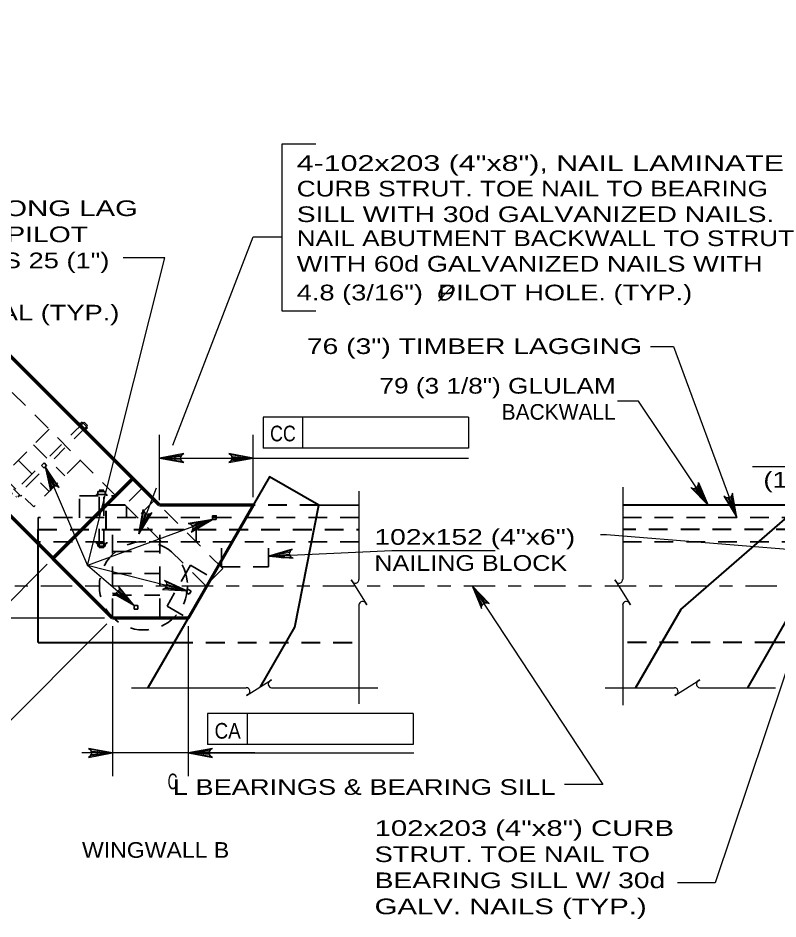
# Model space of a CAD drawing. Extents: x -6.4 to 73.1, y -66 to 0.
# Drawn here: x 21.96 to 27.78, y -57.6 to -50.7 of the extents above; entities that cross this region are included whole.
import ezdxf
from ezdxf.enums import TextEntityAlignment as Align

# ---------------------------------------------------------------- set-up
doc = ezdxf.new("R2010")
doc.units = 0
doc.header["$LTSCALE"] = 0.048
doc.linetypes.add('DOT_DASHED', pattern=[7.7, 5, -1.2, 0.3, -1.2])
doc.linetypes.add('MEDIUM_DASHED', pattern=[4.5, 3, -1.5])
for name, color, linetype, lineweight in [('4', 7, 'Continuous', 25), ('5', 7, 'Continuous', 25), ('52', 7, 'Continuous', 25), ('8', 7, 'Continuous', 25)]:
    doc.layers.add(name, color=color, linetype=linetype, lineweight=lineweight)

msp = doc.modelspace()

# ---------------------------------------------------------------- hatches: boundary and pattern name
at = {"layer": '5'}
for points in [[(23.16208, -54.05267), (23.16208, -54.092), (23.044, -54.07233)], [(23.64475, -54.05267), (23.64475, -54.092), (23.76283, -54.07233)], [(22.169, -54.13942), (22.22433, -54.24425), (22.20617, -54.252)], [(27.46675, -54.52792), (27.41658, -54.42058), (27.43508, -54.41375)], [(23.45042, -54.54325), (23.343, -54.59333), (23.33625, -54.57492)], [(23.87967, -54.82492), (23.99817, -54.82042), (23.99725, -54.84008)], [(23.25542, -55.09025), (23.13842, -55.07083), (23.14325, -55.05175)], [(25.43875, -55.05158), (25.51192, -55.14475), (25.4955, -55.15558)], [(22.84892, -55.20325), (22.75283, -55.13392), (22.76558, -55.119)], [(22.56708, -56.31183), (22.56708, -56.35117), (22.68517, -56.3315)], [(23.38083, -56.31183), (23.38083, -56.35117), (23.26275, -56.3315)]]:
    msp.add_hatch(color=256, dxfattribs=at).paths.add_polyline_path(points)

# ---------------------------------------------------------------- linework, layer by layer
at = {"layer": '4', "lineweight": 70}
for p, q in [((23.044, -54.43392), (21.86292, -53.25283)), ((22.68517, -55.30008), (21.25042, -53.86525)), ((22.83983, -54.22975), (22.22733, -54.84225)), ((23.76283, -54.43392), (23.044, -54.43392)), ((23.76283, -54.43392), (23.26275, -55.30008)), ((23.26275, -55.30008), (22.68517, -55.30008))]:
    msp.add_line(p, q, dxfattribs=at)
at = {"layer": '4', "linetype": 'MEDIUM_DASHED', "lineweight": 35}
for p, q in [((22.70825, -54.36133), (21.73133, -53.38433)), ((22.46633, -53.79667), (22.20417, -54.05883)), ((22.49242, -53.82275), (22.2365, -54.07867)), ((22.19875, -53.85175), (21.84175, -54.20875)), ((22.0795, -53.971), (22.318, -54.20958)), ((21.96058, -54.08992), (22.19917, -54.32842)), ((22.43725, -54.09033), (22.08025, -54.44733)), ((22.092, -54.17092), (21.91817, -54.34483)), ((21.84175, -54.20875), (22.08025, -54.44733)), ((22.12125, -54.19392), (21.94425, -54.37092)), ((22.58133, -54.31917), (22.61825, -54.31917)), ((22.58133, -54.75817), (22.58133, -54.31917)), ((22.61825, -54.75817), (22.61825, -54.31917)), ((22.91242, -54.30242), (22.78092, -54.43392)), ((21.95917, -54.37092), (21.97408, -54.356)), ((22.43117, -54.53), (22.43117, -54.36133)), ((22.43117, -54.36133), (22.70825, -54.36133)), ((22.56025, -54.35075), (22.56025, -54.36133)), ((22.56025, -54.35075), (22.63933, -54.35075)), ((22.57083, -54.32967), (22.57083, -54.35075)), ((22.57083, -54.32967), (22.62883, -54.32967)), ((22.62883, -54.32967), (22.62883, -54.35075)), ((22.63933, -54.35075), (22.63933, -54.36133)), ((23.3985, -55.05158), (22.70825, -54.36133)), ((22.79208, -54.53), (22.79208, -54.44508)), ((23.00642, -54.39642), (22.87492, -54.52792)), ((23.53008, -54.92), (23.044, -54.43392)), ((24.57267, -54.52792), (22.11433, -54.52792)), ((23.324, -54.714), (23.324, -54.52792)), ((26.59325, -54.52792), (29.86575, -54.52792)), ((22.68517, -55.29242), (22.68517, -54.61992)), ((23.04608, -55.29242), (23.04608, -54.61992)), ((24.57267, -54.714), (22.11433, -54.714)), ((23.51875, -54.90642), (23.51875, -54.714)), ((23.87967, -54.90642), (23.87967, -54.714)), ((26.59325, -54.714), (29.86575, -54.714)), ((22.68517, -54.78808), (23.04608, -54.78808)), ((23.28208, -54.8945), (23.44325, -54.9875)), ((23.53008, -54.92), (23.3985, -55.05158)), ((23.51875, -54.90642), (23.87967, -54.90642)), ((22.68517, -54.95617), (23.04608, -54.95617)), ((22.68517, -55.12425), (23.04608, -55.12425)), ((22.68517, -55.29242), (23.04608, -55.29242))]:
    msp.add_line(p, q, dxfattribs=at)
at = {"layer": '4', "lineweight": 35}
for p, q in [((22.42908, -53.80408), (22.42158, -53.81158)), ((22.42908, -53.80408), (22.48492, -53.86)), ((22.45142, -53.79667), (22.4365, -53.81158)), ((22.45142, -53.79667), (22.49242, -53.83767)), ((22.46633, -53.79667), (22.49242, -53.82275)), ((22.49242, -53.83767), (22.4775, -53.85258)), ((22.48492, -53.86), (22.4775, -53.86742)), ((24.264, -54.43392), (24.57267, -54.43392)), ((22.11433, -54.714), (22.11433, -54.52792)), ((22.56025, -54.7265), (22.56025, -54.716)), ((22.56025, -54.7265), (22.63933, -54.7265)), ((22.57083, -54.74758), (22.57083, -54.7265)), ((22.62883, -54.74758), (22.62883, -54.7265)), ((22.63933, -54.7265), (22.63933, -54.716)), ((22.57083, -54.74758), (22.62883, -54.74758)), ((22.58133, -54.75817), (22.61825, -54.75817))]:
    msp.add_line(p, q, dxfattribs=at)
at = {"layer": '4', "linetype": 'MEDIUM_DASHED', "lineweight": 40}
for p, q in [((22.78092, -54.43392), (22.63567, -54.43392)), ((22.63567, -54.61992), (22.63567, -54.43392)), ((24.264, -54.43392), (23.76283, -54.43392)), ((22.11433, -54.61992), (24.57267, -54.61992)), ((29.86575, -54.61992), (26.59325, -54.61992)), ((23.15542, -55.48608), (24.57267, -55.48608)), ((27.75108, -55.48608), (26.59325, -55.48608))]:
    msp.add_line(p, q, dxfattribs=at)
at = {"layer": '4', "lineweight": 40}
for p, q in [((24.08183, -55.3695), (24.264, -54.43392)), ((28.35858, -54.43392), (26.59325, -54.43392)), ((27.03808, -55.23275), (27.957, -54.43392)), ((22.11433, -55.48658), (22.11433, -54.61992)), ((27.03808, -55.23275), (26.69225, -55.83192)), ((23.26275, -55.30008), (22.95575, -55.83192)), ((27.55142, -55.83192), (27.8585, -55.30008)), ((23.81925, -55.82433), (24.08183, -55.3695)), ((22.11433, -55.48608), (23.15542, -55.48608)), ((29.86575, -55.48608), (27.75108, -55.48608))]:
    msp.add_line(p, q, dxfattribs=at)
at = {"layer": '4', "linetype": 'DOT_DASHED'}
msp.add_line((21.5955, -55.05158), (30.39275, -55.05158), dxfattribs=at)
at = {"layer": '4'}
for points in [[(27.24908, -54.43392), (26.71425, -53.63683), (26.55433, -53.63683)], [(28.1095, -54.793), (26.4685, -54.6605), (26.42267, -54.6605)]]:
    msp.add_lwpolyline(points, dxfattribs=at)
at = {"layer": '4', "linetype": 'MEDIUM_DASHED', "lineweight": 35}
for points in [[(22.15917, -54.14933), (22.13942, -54.12958), (22.15917, -54.10983), (22.17892, -54.12958)], [(23.26233, -55.07817), (23.24842, -55.10233), (23.27258, -55.11633), (23.2865, -55.09217)], [(22.84892, -55.23117), (22.87683, -55.23117), (22.87683, -55.20325), (22.84892, -55.20325)]]:
    msp.add_lwpolyline(points, close=True, dxfattribs=at)
at = {"layer": '4', "lineweight": 40}
msp.add_lwpolyline([(24.264, -54.43392), (23.88817, -54.21692), (23.76283, -54.43392)], dxfattribs=at)
at = {"layer": '4', "linetype": 'MEDIUM_DASHED', "lineweight": 35}
for points in [[(21.92558, -54.30758), (21.9815, -54.36342), (21.989, -54.356)], [(23.28208, -54.8945), (23.10167, -55.20708), (23.26275, -55.30008)]]:
    msp.add_lwpolyline(points, dxfattribs=at)
at = {"layer": '4', "lineweight": 35}
msp.add_lwpolyline([(23.47833, -54.54325), (23.45042, -54.54325), (23.45042, -54.51533), (23.47833, -54.51533)], close=True, dxfattribs=at)
at = {"layer": '4', "linetype": 'MEDIUM_DASHED', "lineweight": 35}
msp.add_circle((22.92103, -55.05157), 0.3376, dxfattribs=at)
at = {"layer": '5'}
for p, q in [((23.98267, -51.66758), (23.98267, -52.94567)), ((24.24158, -51.66758), (23.98267, -51.66758)), ((23.98267, -52.94567), (24.24158, -52.94567)), ((26.98392, -53.22058), (26.8075, -53.22058)), ((27.46675, -54.52792), (26.984, -53.22058)), ((25.41225, -53.75975), (23.83742, -53.75975)), ((23.83742, -53.75975), (23.83742, -53.996)), ((24.13992, -53.75975), (24.13992, -53.996)), ((25.41225, -53.75975), (25.41225, -53.996)), ((23.04392, -54.395), (23.04392, -53.89517)), ((23.76283, -54.37242), (23.76283, -53.89517)), ((25.41225, -53.996), (23.83742, -53.996)), ((23.044, -54.07233), (25.41208, -54.07233)), ((27.58925, -54.13692), (28.93608, -54.13692)), ((22.88542, -54.65225), (23.02133, -54.29967)), ((23.45042, -54.54325), (22.49117, -54.89692)), ((22.18392, -54.88575), (21.17033, -55.89925)), ((23.25542, -55.09025), (22.49117, -54.89692)), ((22.84892, -55.20325), (22.49117, -54.89692)), ((27.99592, -55.25533), (27.303, -57.32725)), ((22.64167, -55.34358), (21.62817, -56.35708)), ((22.62358, -55.30008), (21.86433, -55.30008)), ((22.68517, -55.36158), (22.68517, -56.50867)), ((23.26275, -55.36158), (23.26275, -56.50867)), ((24.98708, -56.03067), (23.41225, -56.03067)), ((23.41225, -56.03067), (23.41225, -56.26683)), ((23.71467, -56.03067), (23.71467, -56.26683)), ((24.98708, -56.03067), (24.98708, -56.26683)), ((24.98708, -56.26683), (23.41225, -56.26683)), ((22.68517, -56.3315), (22.449, -56.3315)), ((23.77408, -56.3315), (22.68517, -56.3315)), ((23.26275, -56.3315), (24.99225, -56.3315)), ((27.30292, -57.32725), (27.01375, -57.32725))]:
    msp.add_line(p, q, dxfattribs=at)
at = {"layer": '5', "lineweight": 35}
msp.add_line((25.18292, -52.87183), (25.29492, -52.74925), dxfattribs=at)
at = {"layer": '5'}
for points in [[(23.14667, -53.9745), (23.76233, -52.37725), (23.98258, -52.37725)], [(22.169, -54.13942), (22.49117, -54.89692), (23.08542, -52.53858), (22.76583, -52.53858)], [(23.044, -54.07233), (23.23042, -54.10725), (23.21608, -54.09733), (23.20867, -54.08483), (23.2065, -54.07233), (23.20867, -54.05983), (23.21608, -54.04733), (23.23042, -54.03742), (23.044, -54.07233), (23.21608, -54.04733), (23.20867, -54.05983), (23.044, -54.07233), (23.2065, -54.07233), (23.20867, -54.08483), (23.044, -54.07233), (23.21608, -54.09733)], [(23.76283, -54.07233), (23.57642, -54.03742), (23.59075, -54.04733), (23.59817, -54.05983), (23.60033, -54.07233), (23.59817, -54.08483), (23.59075, -54.09733), (23.57642, -54.10725), (23.76283, -54.07233), (23.59075, -54.09733), (23.59817, -54.08483), (23.76283, -54.07233), (23.60033, -54.07233), (23.59817, -54.05983), (23.76283, -54.07233), (23.59075, -54.04733)], [(22.169, -54.13942), (22.20983, -54.32467), (22.21333, -54.3075), (22.22192, -54.29583), (22.23258, -54.28892), (22.24492, -54.286), (22.25933, -54.28792), (22.27408, -54.29725), (22.169, -54.13942), (22.25933, -54.28792), (22.24492, -54.286), (22.169, -54.13942), (22.23258, -54.28892), (22.22192, -54.29583), (22.169, -54.13942), (22.21333, -54.3075)], [(27.46675, -54.52792), (27.435, -54.34092), (27.43058, -54.35783), (27.42142, -54.36917), (27.4105, -54.3755), (27.398, -54.37783), (27.38367, -54.37517), (27.36942, -54.36517), (27.46675, -54.52792), (27.38367, -54.37517), (27.398, -54.37783), (27.46675, -54.52792), (27.4105, -54.3755), (27.42142, -54.36917), (27.46675, -54.52792), (27.43058, -54.35783)], [(23.45042, -54.54325), (23.26342, -54.57492), (23.28033, -54.57933), (23.29158, -54.5885), (23.29792, -54.5995), (23.30025, -54.61192), (23.29767, -54.62625), (23.28758, -54.6405), (23.45042, -54.54325), (23.29767, -54.62625), (23.30025, -54.61192), (23.45042, -54.54325), (23.29792, -54.5995), (23.29158, -54.5885), (23.45042, -54.54325), (23.28033, -54.57933)], [(23.87967, -54.82492), (24.06875, -54.84008), (24.05342, -54.83167), (24.04475, -54.82), (24.04125, -54.80783), (24.04208, -54.79525), (24.04817, -54.782), (24.06142, -54.7705), (23.87967, -54.82492), (24.04817, -54.782), (24.04208, -54.79525), (23.87967, -54.82492), (24.04125, -54.80783), (24.04475, -54.82), (23.87967, -54.82492), (24.05342, -54.83167)], [(23.87967, -54.82492), (24.82492, -54.78008), (25.61717, -54.78008)], [(22.84892, -55.20325), (22.73008, -55.05542), (22.7345, -55.07233), (22.732, -55.08667), (22.7255, -55.09758), (22.71575, -55.10567), (22.702, -55.11033), (22.68458, -55.10858), (22.84892, -55.20325), (22.702, -55.11033), (22.71575, -55.10567), (22.84892, -55.20325), (22.7255, -55.09758), (22.732, -55.08667), (22.84892, -55.20325), (22.7345, -55.07233)], [(23.25542, -55.09025), (23.08325, -55.01067), (23.09475, -55.02383), (23.09883, -55.03775), (23.09792, -55.05042), (23.09275, -55.062), (23.0825, -55.07233), (23.06608, -55.07842), (23.25542, -55.09025), (23.0825, -55.07233), (23.09275, -55.062), (23.25542, -55.09025), (23.09792, -55.05042), (23.09883, -55.03775), (23.25542, -55.09025), (23.09475, -55.02383)], [(25.43875, -55.05158), (26.44075, -56.57292), (26.14758, -56.57292)], [(25.43875, -55.05158), (25.51208, -55.2265), (25.5125, -55.209), (25.51883, -55.196), (25.52817, -55.18733), (25.53975, -55.18217), (25.55425, -55.1815), (25.5705, -55.188), (25.43875, -55.05158), (25.55425, -55.1815), (25.53975, -55.18217), (25.43875, -55.05158), (25.52817, -55.18733), (25.51883, -55.196), (25.43875, -55.05158), (25.5125, -55.209)], [(22.68517, -56.3315), (22.49875, -56.29658), (22.51308, -56.3065), (22.5205, -56.319), (22.52267, -56.3315), (22.5205, -56.344), (22.51308, -56.3565), (22.49875, -56.36642), (22.68517, -56.3315), (22.51308, -56.3565), (22.5205, -56.344), (22.68517, -56.3315), (22.52267, -56.3315), (22.5205, -56.319), (22.68517, -56.3315), (22.51308, -56.3065)], [(23.26275, -56.3315), (23.44917, -56.36642), (23.43483, -56.3565), (23.42742, -56.344), (23.42525, -56.3315), (23.42742, -56.319), (23.43483, -56.3065), (23.44917, -56.29658), (23.26275, -56.3315), (23.43483, -56.3065), (23.42742, -56.319), (23.26275, -56.3315), (23.42525, -56.3315), (23.42742, -56.344), (23.26275, -56.3315), (23.43483, -56.3565)]]:
    msp.add_lwpolyline(points, dxfattribs=at)
for points in [[(23.16208, -54.05267), (23.16208, -54.092), (23.044, -54.07233)], [(23.64475, -54.05267), (23.64475, -54.092), (23.76283, -54.07233)], [(22.169, -54.13942), (22.22433, -54.24425), (22.20617, -54.252)], [(27.46675, -54.52792), (27.41658, -54.42058), (27.43508, -54.41375)], [(23.45042, -54.54325), (23.343, -54.59333), (23.33625, -54.57492)], [(23.87967, -54.82492), (23.99817, -54.82042), (23.99725, -54.84008)], [(23.25542, -55.09025), (23.13842, -55.07083), (23.14325, -55.05175)], [(25.43875, -55.05158), (25.51192, -55.14475), (25.4955, -55.15558)], [(22.84892, -55.20325), (22.75283, -55.13392), (22.76558, -55.119)], [(22.56708, -56.31183), (22.56708, -56.35117), (22.68517, -56.3315)], [(23.38083, -56.31183), (23.38083, -56.35117), (23.26275, -56.3315)]]:
    msp.add_lwpolyline(points, close=True, dxfattribs=at)
at = {"layer": '5', "lineweight": 35}
msp.add_spline([(25.28325, -52.76133), (25.2745, -52.7545), (25.26575, -52.75208), (25.25475, -52.75108), (25.2485, -52.75108), (25.23775, -52.75358), (25.22792, -52.75808), (25.221, -52.762), (25.20775, -52.77258), (25.19742, -52.78608), (25.19117, -52.79875), (25.1875, -52.81033), (25.18642, -52.82108), (25.1875, -52.83033), (25.192, -52.8435), (25.19675, -52.85033), (25.20642, -52.85758), (25.22092, -52.86108), (25.23742, -52.86058), (25.25825, -52.85108), (25.2735, -52.838), (25.285, -52.82208), (25.2925, -52.8055), (25.295, -52.78708), (25.29175, -52.77525), (25.28375, -52.76133)], degree=3, dxfattribs=at)
at = {"layer": '52'}
for points in [[(27.24908, -54.43392), (27.11617, -54.29858), (27.13242, -54.305), (27.147, -54.30417), (27.1585, -54.299), (27.16775, -54.29025), (27.174, -54.27708), (27.17425, -54.25967), (27.24908, -54.43392), (27.174, -54.27708), (27.16775, -54.29025), (27.24908, -54.43392), (27.1585, -54.299), (27.147, -54.30417), (27.24908, -54.43392), (27.13242, -54.305)], [(22.8855, -54.65225), (22.91992, -54.46567), (22.92408, -54.48267), (22.93308, -54.49408), (22.944, -54.50058), (22.95642, -54.50308), (22.97075, -54.50067), (22.98517, -54.49083), (22.8855, -54.65225), (22.97075, -54.50067), (22.95642, -54.50308), (22.8855, -54.65225), (22.944, -54.50058), (22.93308, -54.49408), (22.8855, -54.65225), (22.92408, -54.48267)]]:
    msp.add_lwpolyline(points, dxfattribs=at)
at = {"layer": '8'}
for p, q in [((26.59325, -54.2955), (26.59325, -55.00267)), ((24.57267, -54.32742), (24.57267, -55.00267)), ((24.57267, -55.19692), (24.57267, -55.95533)), ((26.59325, -55.19692), (26.59325, -55.96492)), ((22.82908, -55.83192), (23.70883, -55.83192)), ((23.90308, -55.83192), (24.71733, -55.83192)), ((26.45942, -55.83192), (26.98983, -55.83192)), ((27.18408, -55.83192), (27.76508, -55.83192))]:
    msp.add_line(p, q, dxfattribs=at)
for points in [[(24.51967, -55.01683), (24.51225, -55.00483), (24.63317, -55.19733), (24.62508, -55.18442)], [(26.54025, -55.01683), (26.53275, -55.00483), (26.65367, -55.19733), (26.64558, -55.18442)], [(23.723, -55.88492), (23.711, -55.89233), (23.90342, -55.77142), (23.89058, -55.7795)], [(27.004, -55.88492), (26.992, -55.89233), (27.1845, -55.77142), (27.17158, -55.7795)]]:
    msp.add_lwpolyline(points, dxfattribs=at)
for centre, start, end in [((24.54422, -55.00266), 210, 0), ((26.56475, -55.00266), 210, 0), ((24.60092, -55.19955), 32.13276, 174.67141), ((26.62145, -55.19955), 32.13276, 174.67141), ((23.70873, -55.8603), 300, 90), ((23.90561, -55.8036), 122.13276, 264.67141), ((26.98974, -55.8603), 300, 90), ((27.18663, -55.8036), 122.13276, 264.67141)]:
    msp.add_arc(centre, 0.02841, start, end, dxfattribs=at)

# ---------------------------------------------------------------- texts
at = {"layer": '5', "width": 1.5}
msp.add_text('890 (3\'-0") MIN. SPACING', height=0.12, rotation=45, dxfattribs=at).set_placement((21.30657, -49.79276), align=Align.CENTER)
at = {"layer": '5'}
for s, width, p in [('4-102x203 (4"x8"), NAIL LAMINATED,', 1.45, (24.09558, -51.873)), ('CURB STRUT. TOE NAIL TO BEARING', 1.25, (24.09558, -52.06883)), ('12.7 (1/2")  x 254 (10") LONG LAG', 1.4, (19.40975, -52.21883)), ('SILL WITH 30d GALVANIZED NAILS.', 1.35, (24.09558, -52.26467)), ('SCREWS W/ 7.9 (5/16")  PILOT', 1.35, (19.40975, -52.41883)), ('NAIL ABUTMENT BACKWALL TO STRUT ', 1.25, (24.09558, -52.44883)), ('HOLE.  RECESS SCREWS 25 (1")', 1.3, (19.40975, -52.61883)), ('WITH 60d GALVANIZED NAILS WITH', 1.3, (24.09558, -52.64467)), ('4.8 (3/16")  PILOT HOLE. (TYP.)', 1.3, (24.09558, -52.86458)), ('JOINT SEALING MATERIAL (TYP.)', 1.3, (19.40975, -53.01883)), ('76 (3") TIMBER LAGGING', 1.35, (24.17325, -53.27558)), ('102x152 (4"x6")', 1.35, (24.69075, -54.73708)), ('NAILING BLOCK', 1.2, (24.69075, -54.93708)), ('C', 0.65, (23.10642, -56.60992)), ('L BEARINGS & BEARING SILL', 1.3, (23.1455, -56.65292)), ('102x203 (4"x8") CURB', 1.4, (24.69242, -56.96767)), ('WINGWALL B', 1.1, (22.45042, -57.13525)), ('STRUT. TOE NAIL TO', 1.3, (24.69242, -57.16767)), ('BEARING SILL W/ 30d', 1.35, (24.69242, -57.36767)), ('GALV. NAILS (TYP.)', 1.4, (24.69242, -57.56767))]:
    msp.add_text(s, height=0.12, dxfattribs=dict(at, width=width)).set_placement(p)
at = {"layer": '5', "width": 1.25}
msp.add_text('79 (3 1/8") GLULAM', height=0.12, dxfattribs=at).set_placement((26.53992, -53.57917), align=Align.RIGHT)
at = {"layer": '5'}
msp.add_text('BACKWALL', height=0.12, dxfattribs=at).set_placement((26.53992, -53.77917), align=Align.RIGHT)
for s, width, p in [('CC', 0.85, (23.98996, -53.94458)), ('(1\'-0")', 1.3, (27.94854, -54.29858)), ('CA', 0.9, (23.56629, -56.22233))]:
    msp.add_text(s, height=0.12, dxfattribs=dict(at, width=width)).set_placement(p, align=Align.CENTER)

doc.saveas('drawing.dxf')
